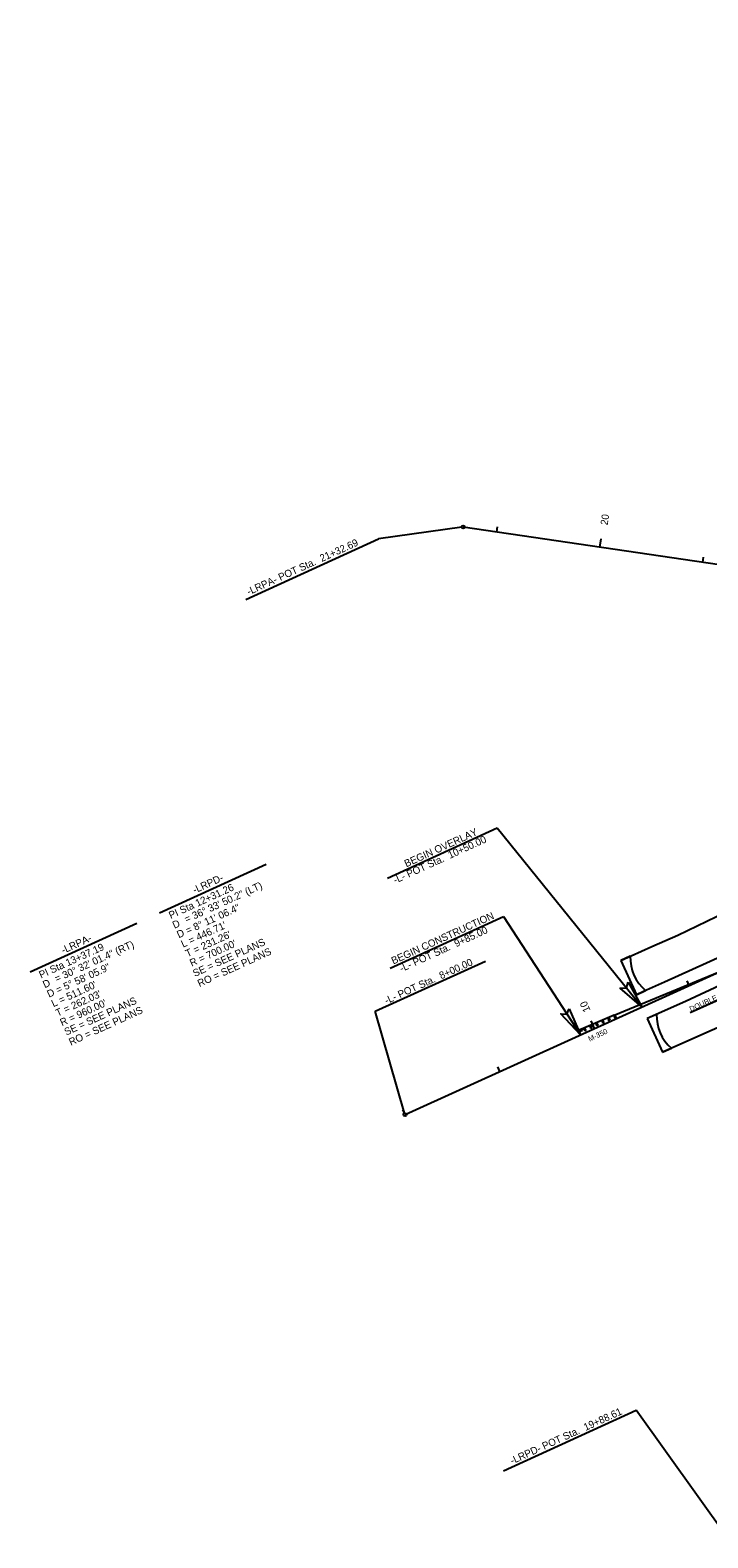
# Model space of a CAD drawing. Extents: x 2242984 to 2250974, y 661492 to 664681.
# Drawn here: x 2247141 to 2247792, y 662299 to 663746 of the extents above; entities that cross this region are included whole.
import ezdxf

# ---------------------------------------------------------------- set-up
doc = ezdxf.new("R2010")
doc.units = 0
for name, color, linetype in [('Prop DSN Text', 7, 'Continuous'), ('Prop Guardrail Anchor Unit CELL', 7, 'Continuous'), ('Prop Guardrail Double Faced', 7, 'Continuous'), ('Prop Horizontal Alignment', 7, 'Continuous'), ('Prop Horizontal Alignment Curve and Spiral Data', 7, 'Continuous'), ('Prop Horizontal Alignment Station Label', 7, 'Continuous'), ('Prop Horizontal Alignment Tick Label', 7, 'Continuous'), ('Prop Horizontal Alignment Tick Large', 7, 'Continuous'), ('Prop Horizontal Alignment Tick Small', 7, 'Continuous'), ('Prop Paved Shoulder', 7, 'Continuous'), ('Prop Shade Medium', 7, 'Continuous'), ('Prop Terminator CELL', 7, 'Continuous'), ('Scratch_Level_2', 7, 'Continuous')]:
    doc.layers.add(name, color=color, linetype=linetype)

msp = doc.modelspace()

# ---------------------------------------------------------------- linework, layer by layer
at = {"layer": 'Prop DSN Text'}
msp.add_line((2247835.4, 662830.2), (2247774.8, 662802.6), dxfattribs=at)
at = {"layer": 'Prop Guardrail Anchor Unit CELL'}
for p, q in [((2247701.8, 662800.5), (2247670.2, 662787.2)), ((2247689.7, 662795.4), (2247690.9, 662792.7)), ((2247691.2, 662794.4), (2247689.7, 662795.4)), ((2247690.6, 662795.8), (2247690.3, 662794)), ((2247690.6, 662795.8), (2247691.8, 662793.1)), ((2247695.5, 662797.9), (2247696.7, 662795.2)), ((2247697, 662796.9), (2247695.5, 662797.9)), ((2247696.5, 662798.3), (2247696.1, 662796.5)), ((2247697, 662796.9), (2247696.1, 662796.5)), ((2247696.1, 662796.5), (2247697.6, 662795.6)), ((2247696.5, 662798.3), (2247697.6, 662795.6)), ((2247696.7, 662795.2), (2247697, 662796.9)), ((2247697.6, 662795.6), (2247696.7, 662795.2)), ((2247701.3, 662800.3), (2247702.5, 662797.6)), ((2247702.8, 662799.3), (2247701.3, 662800.3)), ((2247702.3, 662800.7), (2247701.9, 662798.9)), ((2247702.8, 662799.3), (2247701.9, 662798.9)), ((2247701.9, 662798.9), (2247703.4, 662798)), ((2247702.3, 662800.7), (2247703.4, 662798)), ((2247702.5, 662797.6), (2247702.8, 662799.3)), ((2247703.4, 662798), (2247702.5, 662797.6)), ((2247670.2, 662787.2), (2247668.1, 662786.3)), ((2247669.5, 662786.9), (2247669.8, 662786.3)), ((2247669.5, 662786.9), (2247669.8, 662786.3)), ((2247669.5, 662786.9), (2247670.1, 662785.4)), ((2247669.5, 662786.9), (2247671.4, 662786)), ((2247669.5, 662785.2), (2247669.8, 662786.3)), ((2247670.8, 662787.4), (2247670.1, 662785.4)), ((2247670.1, 662785.4), (2247671.4, 662786)), ((2247670.2, 662787.2), (2247670.5, 662786.4)), ((2247671.4, 662786), (2247670.8, 662787.4)), ((2247672.3, 662788.1), (2247673.5, 662785.4)), ((2247673.8, 662787.1), (2247672.3, 662788.1)), ((2247672.8, 662788.3), (2247673.1, 662787.6)), ((2247673.2, 662788.5), (2247672.9, 662786.7)), ((2247673.8, 662787.1), (2247672.9, 662786.7)), ((2247672.9, 662786.7), (2247674.4, 662785.8)), ((2247673.2, 662788.5), (2247674.4, 662785.8)), ((2247673.5, 662785.4), (2247673.8, 662787.1)), ((2247674.4, 662785.8), (2247673.5, 662785.4)), ((2247678.1, 662790.5), (2247679.3, 662787.8)), ((2247679.6, 662789.5), (2247678.1, 662790.5)), ((2247679, 662790.9), (2247678.7, 662789.1)), ((2247679.6, 662789.5), (2247678.7, 662789.1)), ((2247678.7, 662789.1), (2247680.2, 662788.2)), ((2247679, 662790.9), (2247680.2, 662788.2)), ((2247679.3, 662787.8), (2247679.6, 662789.5)), ((2247680.2, 662788.2), (2247679.3, 662787.8)), ((2247683.9, 662793), (2247685.1, 662790.3)), ((2247685.4, 662792), (2247683.9, 662793)), ((2247684.8, 662793.4), (2247684.5, 662791.6)), ((2247685.4, 662792), (2247684.5, 662791.6)), ((2247684.5, 662791.6), (2247686, 662790.7)), ((2247684.8, 662793.4), (2247686, 662790.7)), ((2247685.1, 662790.3), (2247685.4, 662792)), ((2247686, 662790.7), (2247685.1, 662790.3)), ((2247691.2, 662794.4), (2247690.3, 662794)), ((2247690.3, 662794), (2247691.8, 662793.1)), ((2247690.9, 662792.7), (2247691.2, 662794.4)), ((2247691.8, 662793.1), (2247690.9, 662792.7))]:
    msp.add_line(p, q, dxfattribs=at)
msp.add_ellipse((2247668.5, 662785.4), major_axis=(0.386, -0.915), ratio=0.995379, start_param=3.141593, end_param=7.214552, dxfattribs=at)
at = {"layer": 'Prop Guardrail Double Faced'}
msp.add_line((2247701.8, 662800.5), (2247806.4, 662843.8), dxfattribs=at)
at = {"layer": 'Prop Horizontal Alignment'}
for p, q in [((2247500.8, 662705), (2249793.1, 663746.3)), ((2248096.7, 663189.5), (2247556.6, 663269.2))]:
    msp.add_line(p, q, dxfattribs=at)
at = {"layer": 'Prop Horizontal Alignment Station Label'}
for p, q in [((2247347.7, 663199.7), (2247475.2, 663257.8)), ((2247555.2, 663269), (2247475.2, 663257.8)), ((2247483.9, 662932.2), (2247589.4, 662980.3)), ((2247589.4, 662980.3), (2247728.4, 662808.4)), ((2247264.7, 662898.7), (2247367.3, 662945.5)), ((2247140.6, 662842.2), (2247243.2, 662888.9)), ((2247486.4, 662845.7), (2247595.5, 662895.4)), ((2247595.5, 662895.4), (2247669.2, 662781.5)), ((2247472.1, 662804.3), (2247578, 662852.5)), ((2247500.4, 662706.5), (2247472.1, 662804.3)), ((2247595.3, 662363.1), (2247722.8, 662421.2)), ((2247810.6, 662298.6), (2247722.8, 662421.2))]:
    msp.add_line(p, q, dxfattribs=at)
for centre in [(2247556.6, 663269.2), (2247500.8, 662705)]:
    msp.add_circle(centre, 1.5, dxfattribs=at)
at = {"layer": 'Prop Horizontal Alignment Tick Large'}
for p, q in [((2247687.9, 663249.8), (2247689.1, 663257.8)), ((2247682.9, 662787.7), (2247679.6, 662795))]:
    msp.add_line(p, q, dxfattribs=at)
at = {"layer": 'Prop Horizontal Alignment Tick Small'}
for p, q in [((2247589, 663264.5), (2247589.7, 663269.4)), ((2247786.8, 663235.2), (2247787.6, 663240.2)), ((2247773.9, 662829.1), (2247771.9, 662833.6)), ((2247591.8, 662746.4), (2247589.8, 662750.9)), ((2247500.8, 662705), (2247498.7, 662709.6))]:
    msp.add_line(p, q, dxfattribs=at)
at = {"layer": 'Prop Paved Shoulder'}
for points in [[(2247708.2, 662853), (2247737.8, 662866.5), (2247762.8, 662877.4), (2247800.1, 662895.1), (2247832.4, 662909.7), (2247861.6, 662923.2), (2247885.3, 662933.8), (2247909.6, 662945.1), (2247924.9, 662952), (2247966.3, 662970.9), (2247994.5, 662983.9), (2248025.6, 662998.2), (2248058.1, 663013), (2248088.1, 663026.4), (2248119.8, 663041.1), (2248150.2, 663054.4), (2248181.1, 663069.6), (2248183, 663070.5)], [(2247748.1, 662765), (2247749.9, 662765.8), (2247788, 662782.9), (2247819.9, 662797), (2247858.4, 662814.5), (2247890.5, 662828.5), (2247929.8, 662846.1), (2247965.8, 662862.2), (2248016.3, 662884.7), (2248053.9, 662901.1), (2248085.7, 662916.5), (2248123.2, 662934.3), (2248153.9, 662949.1), (2248186.4, 662964.7), (2248216.9, 662976.7)], [(2247868.3, 662885.7), (2247836.9, 662871.4), (2247807.3, 662858), (2247776.9, 662844.2), (2247750.2, 662832.3), (2247729.9, 662823.2), (2247723.1, 662820.1)], [(2247869.6, 662860.2), (2247822.9, 662838), (2247808.1, 662831.3), (2247770.2, 662813.7), (2247733.5, 662797.2)]]:
    msp.add_lwpolyline(points, dxfattribs=at)
at = {"layer": 'Prop Shade Medium'}
for p, q in [((2247717.1, 662857.1), (2247708.2, 662853)), ((2247708.2, 662853), (2247723.1, 662820.1)), ((2247723.1, 662820.1), (2247731.9, 662824.1)), ((2247742.5, 662801.2), (2247733.5, 662797.2)), ((2247733.5, 662797.2), (2247748.1, 662765)), ((2247748.1, 662765), (2247756.7, 662768.9))]:
    msp.add_line(p, q, dxfattribs=at)
for centre, radius, start, end in [((2247758.6, 662855.9), 41.5, 178.3201, 230.0155), ((2247783, 662799.7), 40.5, 177.813, 229.5085)]:
    msp.add_arc(centre, radius, start, end, dxfattribs=at)
at = {"layer": 'Prop Terminator CELL'}
for points in [[(2247715.1, 662832.3), (2247728.4, 662808.4), (2247707.6, 662826.5), (2247713.5, 662826.8)], [(2247658.5, 662806.7), (2247669.2, 662781.5), (2247650.4, 662801.7), (2247656.3, 662801.4)]]:
    msp.add_lwpolyline(points, close=True, dxfattribs=at)
at = {"layer": 'Scratch_Level_2'}
for points in [[(2247708.2, 662853), (2247737.8, 662866.5), (2247762.8, 662877.4), (2247800.1, 662895.1), (2247832.4, 662909.7), (2247861.6, 662923.2), (2247885.3, 662933.8), (2247909.6, 662945.1), (2247924.9, 662952), (2247966.3, 662970.9), (2247994.5, 662983.9), (2248025.6, 662998.2), (2248058.1, 663013), (2248088.1, 663026.4), (2248119.8, 663041.1), (2248150.2, 663054.4), (2248181.1, 663069.6), (2248183, 663070.5)], [(2247748.1, 662765), (2247749.9, 662765.8), (2247788, 662782.9), (2247819.9, 662797), (2247858.4, 662814.5), (2247890.5, 662828.5), (2247929.8, 662846.1), (2247965.8, 662862.2), (2248016.3, 662884.7), (2248053.9, 662901.1), (2248085.7, 662916.5), (2248123.2, 662934.3), (2248153.9, 662949.1), (2248186.4, 662964.7), (2248216.9, 662976.7)]]:
    msp.add_lwpolyline(points, dxfattribs=at)

# ---------------------------------------------------------------- texts
at = {"layer": 'Prop DSN Text'}
msp.add_text('DOUBLE FACED GR', height=5, rotation=24.4979, dxfattribs=at).set_placement((2247775.4, 662803.8))
at = {"layer": 'Prop Guardrail Anchor Unit CELL'}
msp.add_text('M-350', height=5, rotation=24.4301, dxfattribs=at).set_placement((2247678.1, 662775.1))
at = {"layer": 'Prop Horizontal Alignment Curve and Spiral Data'}
for s, p in [('PI Sta 12+31.26', (2247275.7, 662892.8)), ('= 36%%d 33\' 50.2" (LT)', (2247290.8, 662889)), ('-LRPD-', (2247298.6, 662917.1)), ('D = 8%%d 11\' 06.4"', (2247283.4, 662874.3)), ('D', (2247279.2, 662883.4)), ("L = 446.71'", (2247287.5, 662865.2)), ("T = 231.26'", (2247291.7, 662856.1)), ('PI Sta 13+37.19', (2247151, 662835.6)), ('= 30%%d 32\' 01.4" (RT)', (2247166.1, 662831.9)), ('-LRPA-', (2247172.4, 662859.3)), ("R = 700.00'", (2247295.8, 662847)), ('SE = SEE PLANS', (2247298.8, 662837.1)), ('RO = SEE PLANS', (2247303.3, 662827.4)), ('D = 5%%d 58\' 05.9"', (2247158.7, 662817.2)), ('D', (2247154.6, 662826.3)), ("L = 511.60'", (2247162.9, 662808.1)), ("T = 262.03'", (2247167, 662799)), ("R = 960.00'", (2247171.2, 662789.9)), ('SE = SEE PLANS', (2247175.3, 662780.8)), ('RO = SEE PLANS', (2247179.7, 662771.1))]:
    msp.add_text(s, height=7, rotation=24.4979, dxfattribs=at).set_placement(p)
at = {"layer": 'Prop Horizontal Alignment Station Label'}
for s, p in [('-LRPA- POT Sta.  21+32.69', (2247350.7, 663203.6)), ('-L- POT Sta.  10+50.00', (2247491.4, 662926.6)), ('BEGIN OVERLAY', (2247502, 662942.4)), ('BEGIN CONSTRUCTION', (2247489.5, 662849.1)), ('-L- POT Sta.  9+85.00', (2247497.4, 662841.7)), ('-L- POT Sta.  8+00.00', (2247483, 662810.9)), ('-LRPD- POT Sta.  19+88.61', (2247603.7, 662369.1))]:
    msp.add_text(s, height=7, rotation=24.4979, dxfattribs=at).set_placement(p)
at = {"layer": 'Prop Horizontal Alignment Tick Label'}
for s, rotation, p in [('20', 81.5964, (2247695.4, 663270.7)), ('10', 114.4301, (2247679.1, 662805.3))]:
    msp.add_text(s, height=7, rotation=rotation, dxfattribs=at).set_placement(p)

doc.saveas('drawing.dxf')
